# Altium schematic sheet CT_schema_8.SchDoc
size 277 x 170 mm
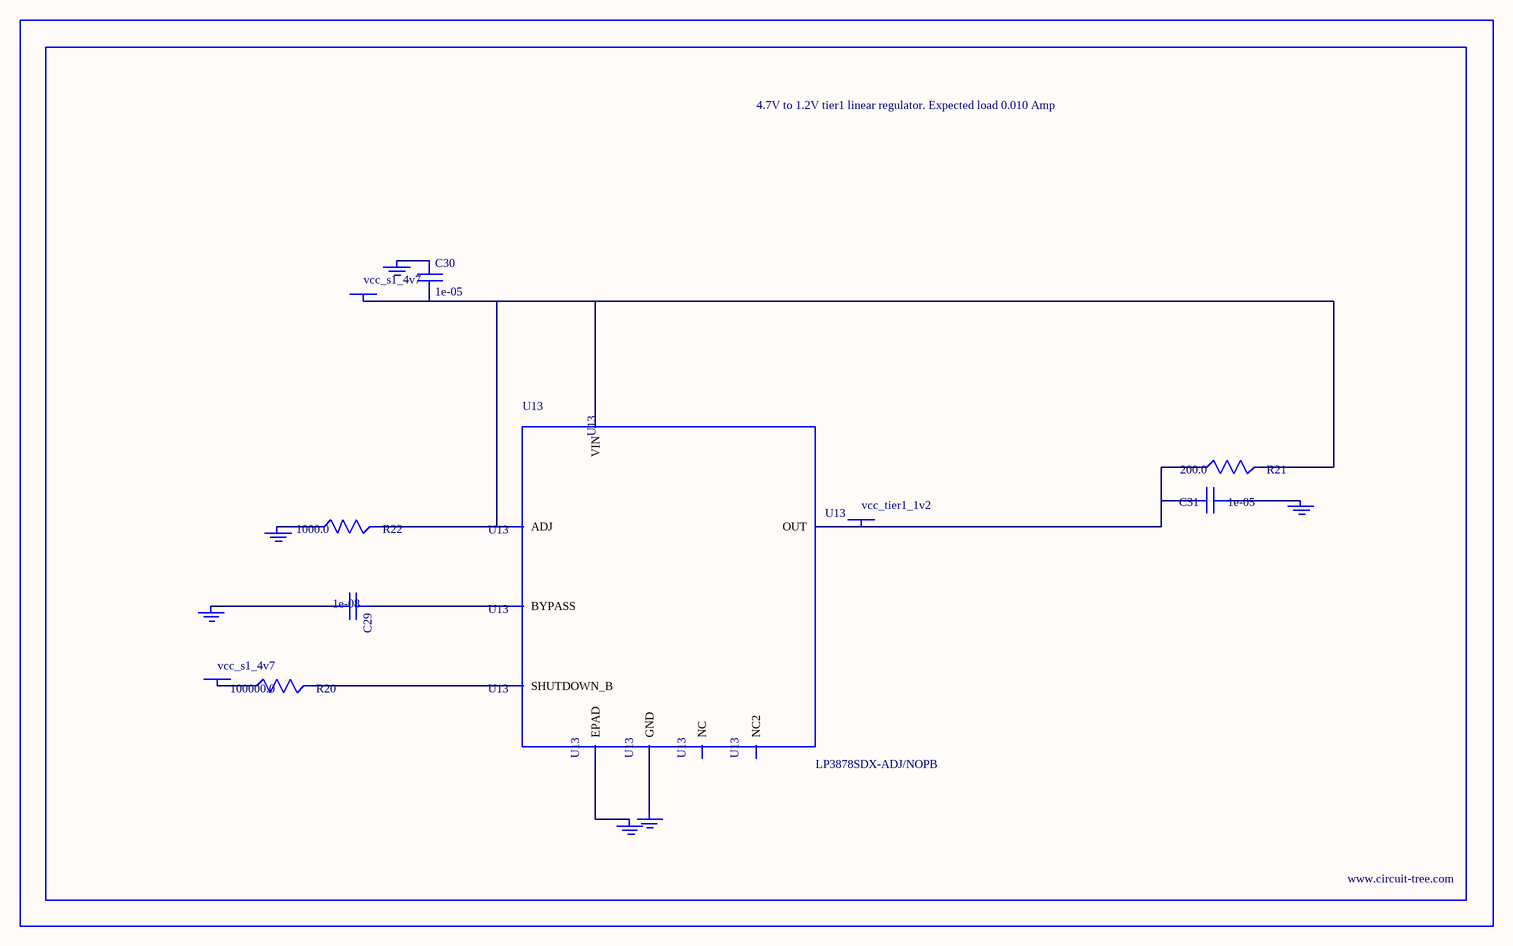
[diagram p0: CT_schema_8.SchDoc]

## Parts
BORDER7  (no value)
C29  1e-08  [C0402]
C30  1e-05  [C1206]
C31  1e-05  [C0805]
GND_INSTANCE_7_0  (no value)
GND_INSTANCE_7_1  (no value)
GND_INSTANCE_7_2  (no value)
GND_INSTANCE_7_3  (no value)
GND_INSTANCE_7_4  (no value)
GND_INSTANCE_7_5  (no value)
POWER_INSTANCE_7_0  vcc_s1_4v7
POWER_INSTANCE_7_1  vcc_s1_4v7
POWER_INSTANCE_7_2  vcc_tier1_1v2
R20  100000.0  [R0603]
R21  200.0  [R0603]
R22  1000.0  [R0603]
U13  LP3878SDX-ADJ/NOPB  [WSON-8]

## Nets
NetC29_1: C29.1 U13.1(BYPASS)
NetC29_2: C29.2 GND_INSTANCE_7_0.0(GND)
NetC30_1: C30.1 GND_INSTANCE_7_1.0(GND)
NetC30_2: C30.2 POWER_INSTANCE_7_0.0(PWR) R21.2 R22.2 U13.4(VIN) U13.6(ADJ)
NetC31_1: C31.1 GND_INSTANCE_7_2.0(GND)
NetC31_2: C31.2 POWER_INSTANCE_7_2.0(PWR) R21.1 U13.5(OUT)
NetGND_INSTANCE_7_3_0: GND_INSTANCE_7_3.0(GND) R22.1
NetGND_INSTANCE_7_4_0: GND_INSTANCE_7_4.0(GND) U13.PAD(EPAD)
NetGND_INSTANCE_7_5_0: GND_INSTANCE_7_5.0(GND) U13.3(GND)
NetPOWER_INSTANCE_7_1_0: POWER_INSTANCE_7_1.0(PWR) R20.1
NetR20_2: R20.2 U13.8(SHUTDOWN_B)

Not connected (* = marked no-connect by the designer): U13 2(NC) 7(NC2)

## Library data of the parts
BORDER7 = BORDER_PAGE7
C29 = C0402C103K3RAC
C30 = C1206C106K3RACTU
C31 = GRM219R60J106ME19D
GND_INSTANCE_7_0-GND_INSTANCE_7_5 = GND
POWER_INSTANCE_7_0-POWER_INSTANCE_7_2 = PWR
R20 = RC0603JR-07100KL
R21 = RC0603JR-07200RL
R22 = RC0603JR-071KL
